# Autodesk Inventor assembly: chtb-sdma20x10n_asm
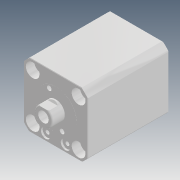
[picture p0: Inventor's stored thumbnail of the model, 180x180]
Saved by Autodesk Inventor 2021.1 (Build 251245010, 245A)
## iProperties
Created: 2018-05
Part Number: chtb-sdma20x10n_asm
Description: STEP AP214
Document SubType Name: Assembly
Designer: user
Title: chtb-sdma20x10n_asm.STEP
Revision Number: ÈÎºÎ
Sending System: SolidWorks 2016
Preprocessor: SwSTEP 2.0
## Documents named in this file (5)
- D:\Vault_2016\Projekty\Clamptek\Hydraulic\CHTB\CHTB-20\Inventor\CHTB-SDMA20x10N\chtb-sdma20x10n_asm.iam
- D:\Vault_2016\Projekty\Clamptek\Hydraulic\CHTB\CHTB-20\Inventor\CHTB-SDMA20x10N\CHTB-SDMA20X10NBT.ipt
- D:\Vault_2016\Projekty\Clamptek\Hydraulic\CHTB\CHTB-20\Inventor\CHTB-SDMA20x10N\CHTB-SDMA20X10NHSG.ipt
- D:\Vault_2016\Projekty\Clamptek\Hydraulic\CHTB\CHTB-20\Inventor\CHTB-SDMA20x10N\QG_3.ipt
- D:\Vault_2016\Projekty\Clamptek\Hydraulic\CHTB\CHTB-20\Inventor\CHTB-SDMA20x10N\socket set screw flat point_iso_ISO 4026 - M5 x 5-N.ipt
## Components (5 placed, 5 different names)
1. CHTB-SDMA20X10NBT_1
2. CHTB-SDMA20X10NHSG_2
3. QG_3_3
4. socket set screw flat point_iso_ISO 4026 - M5 x 5-N_4
5. socket set screw flat point_iso_ISO 4026 - M5 x 5-N_5
